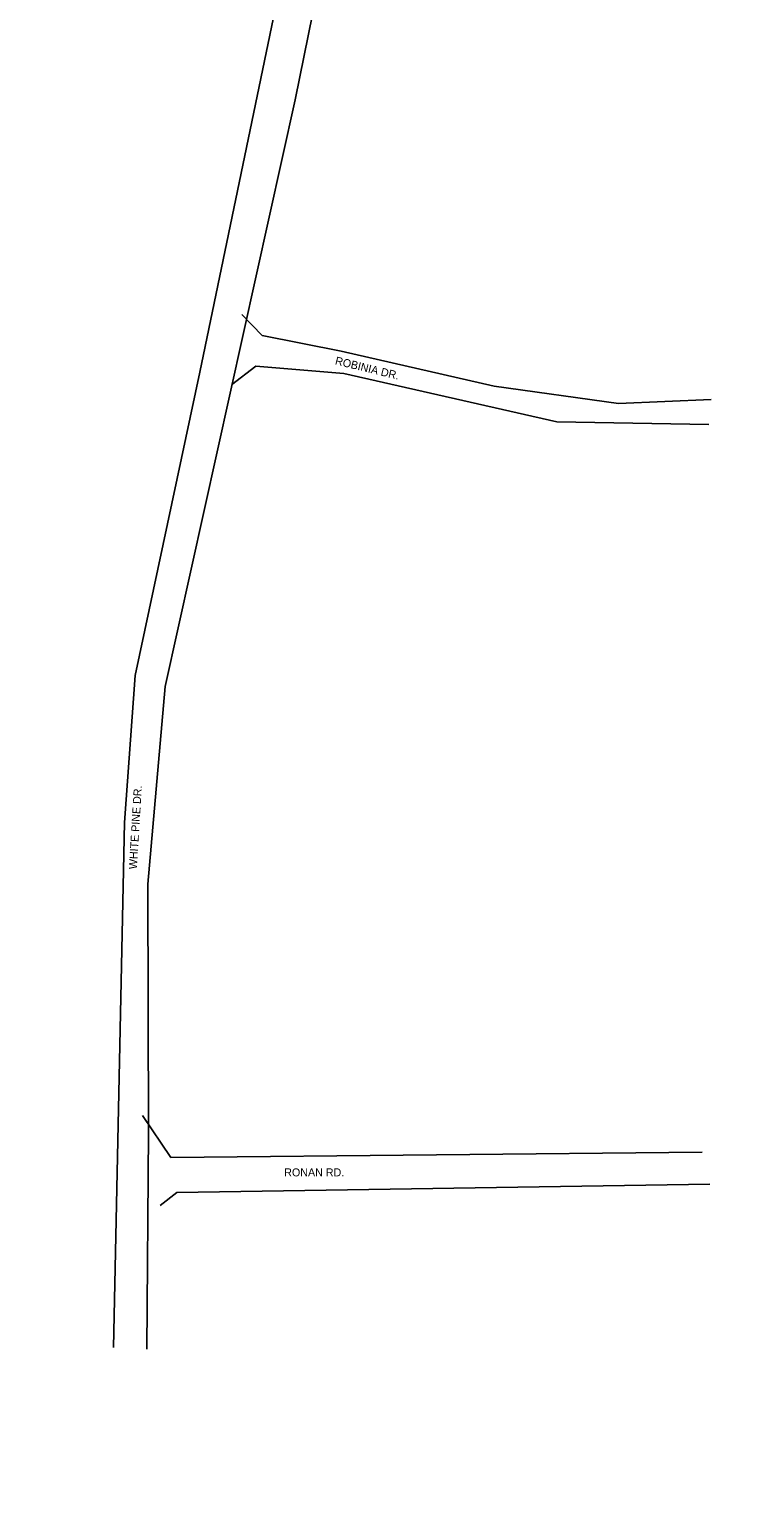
# Model space of a CAD drawing. Extents: x 227157 to 233208, y 434992 to 456232.
# Drawn here: x 230435 to 231057, y 453528 to 454815 of the extents above; entities that cross this region are included whole.
import ezdxf

# ---------------------------------------------------------------- set-up
doc = ezdxf.new("R2010")
doc.units = 0
for name, color, linetype in [('GE_X_Alignment', 7, 'Continuous'), ('PM_X_Edge_Line', 7, 'Continuous'), ('PM_X_Lane_Line', 7, 'Continuous'), ('PV_X_EOP', 7, 'Continuous'), ('SV_X_Text_Name', 7, 'Continuous')]:
    doc.layers.add(name, color=color, linetype=linetype)

msp = doc.modelspace()

# ---------------------------------------------------------------- linework, layer by layer
at = {"layer": 'GE_X_Alignment'}
for centre, radius, start, end in [((98156.5, 484872.4), 135380, 346.901604, 347.729575), ((384495.2, 417626.5), 158620, 166.15811, 166.912499)]:
    msp.add_arc(centre, radius, start, end, dxfattribs=at)
at = {"layer": 'PM_X_Edge_Line'}
for centre, radius, start, end in [((98156.5, 484872.4), 135380, 346.901604, 347.729575), ((384495.2, 417626.5), 158620, 166.15811, 166.912499), ((384495.2, 417626.5), 158572, 166.15811, 166.48524), ((384495.2, 417626.5), 158560, 166.15811, 166.912499)]:
    msp.add_arc(centre, radius, start, end, dxfattribs=at)
at = {"layer": 'PM_X_Lane_Line'}
for radius, start in [(158608, 166.15811), (158596, 166.15811), (158584, 166.227133)]:
    msp.add_arc((384495.2, 417626.5), radius, start, 166.48524, dxfattribs=at)
at = {"layer": 'PV_X_EOP'}
for points in [[(230508.4, 453661.7), (230517.9, 454121), (230527.3, 454249.6), (230583.9, 454514.9), (230874.3, 455913.3), (230908, 455985.3), (231056.8, 455983.2)], [(231052.7, 455957.2), (230940.3, 455947.9), (230904.9, 455924.1), (230834.4, 455575.9), (230667.4, 454753.2), (230553.6, 454240.1), (230538.5, 454067.2), (230538.9, 453849.4), (230537.6, 453660.4)], [(231031.2, 454491.1), (230950.1, 454487.7), (230841.2, 454502.8), (230707.5, 454533.3), (230638.5, 454547), (230620.5, 454565.4)], [(230611.7, 454503.9), (230632.9, 454520.2), (230709.7, 454513.9), (230896.1, 454471.6), (231028.9, 454469.1)], [(231023.1, 453832.8), (230558.6, 453827.9), (230533.7, 453864.8)], [(230549.2, 453786), (230563.8, 453797.5), (231029.8, 453804.8)]]:
    msp.add_lwpolyline(points, dxfattribs=at)
for centre, radius, start, end in [((98156.5, 484872.4), 135392, 346.901604, 347.729575), ((384495.2, 417626.5), 158632, 166.15811, 166.912499), ((384495.2, 417626.5), 158548, 166.15811, 166.912499)]:
    msp.add_arc(centre, radius, start, end, dxfattribs=at)

# ---------------------------------------------------------------- texts
at = {"layer": 'SV_X_Text_Name'}
for s, rotation, p in [('ROBINIA DR.', 346.2714, (230701.7, 454521.9)), ('WHITE PINE DR.', 86.5195, (230528.8, 454080))]:
    msp.add_text(s, height=7, rotation=rotation, dxfattribs=at).set_placement(p)
msp.add_text('RONAN RD.', height=7, dxfattribs=at).set_placement((230657.7, 453811.5))

doc.saveas('drawing.dxf')
